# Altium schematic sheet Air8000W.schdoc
size 264 x 132 mm
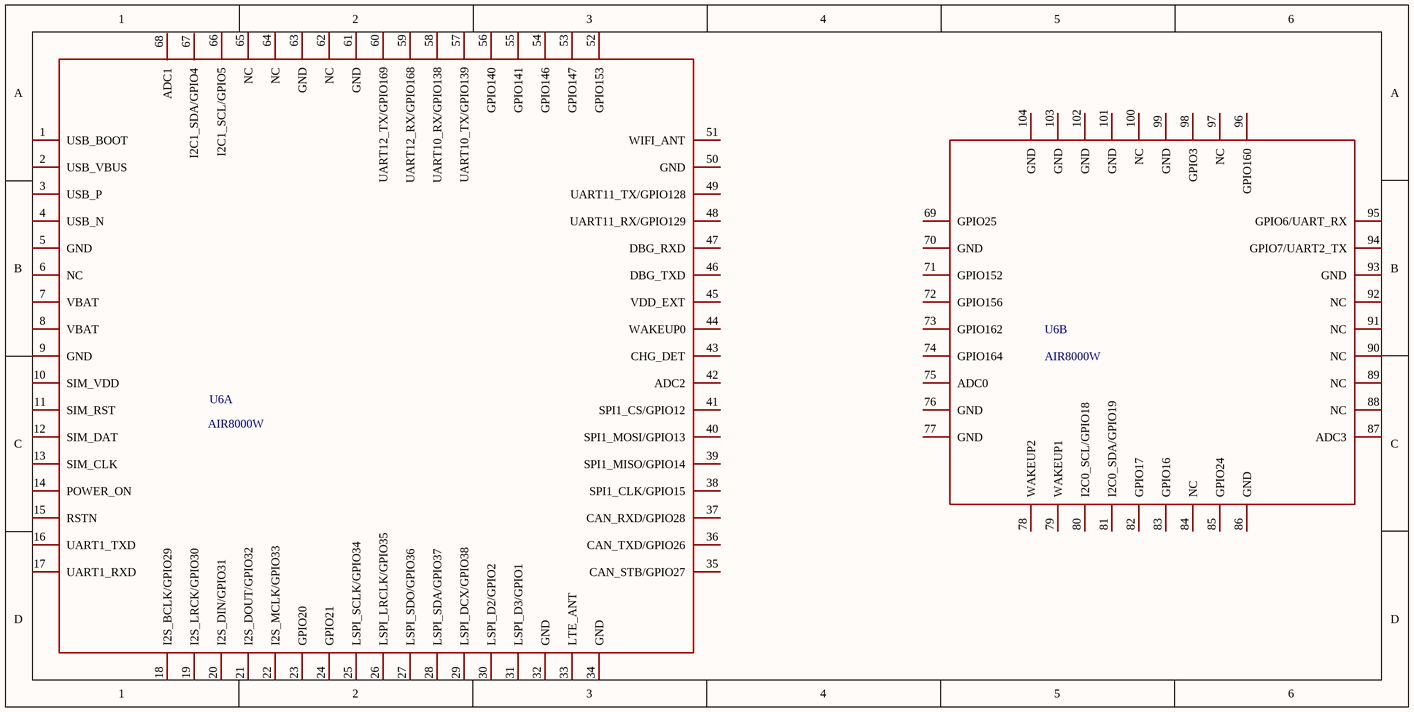
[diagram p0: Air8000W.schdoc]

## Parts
U6  AIR8000W  (parts A,B of 2)

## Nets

Not connected (* = marked no-connect by the designer): U6 1(USB_BOOT) 2(USB_VBUS) 3(USB_P) 4(USB_N) 5(GND) 6(NC) 7(VBAT) 8(VBAT) 9(GND) 10(SIM_VDD) 11(SIM_RST) 12(SIM_DAT) 13(SIM_CLK) 14(POWER_ON) 15(RSTN) 16(UART1_TXD) 17(UART1_RXD) 18(I2S_BCLK/GPIO29) 19(I2S_LRCK/GPIO30) 20(I2S_DIN/GPIO31) 21(I2S_DOUT/GPIO32) 22(I2S_MCLK/GPIO33) 23(GPIO20) 24(GPIO21) 25(LSPI_SCLK/GPIO34) 26(LSPI_LRCLK/GPIO35) 27(LSPI_SDO/GPIO36) 28(LSPI_SDA/GPIO37) 29(LSPI_DCX/GPIO38) 30(LSPI_D2/GPIO2) 31(LSPI_D3/GPIO1) 32(GND) 33(LTE_ANT) 34(GND) 35(CAN_STB/GPIO27) 36(CAN_TXD/GPIO26) 37(CAN_RXD/GPIO28) 38(SPI1_CLK/GPIO15) 39(SPI1_MISO/GPIO14) 40(SPI1_MOSI/GPIO13) 41(SPI1_CS/GPIO12) 42(ADC2) 43(CHG_DET) 44(WAKEUP0) 45(VDD_EXT) 46(DBG_TXD) 47(DBG_RXD) 48(UART11_RX/GPIO129) 49(UART11_TX/GPIO128) 50(GND) 51(WIFI_ANT) 52(GPIO153) 53(GPIO147) 54(GPIO146) 55(GPIO141) 56(GPIO140) 57(UART10_TX/GPIO139) 58(UART10_RX/GPIO138) 59(UART12_RX/GPIO168) 60(UART12_TX/GPIO169) 61(GND) 62(NC) 63(GND) 64(NC) 65(NC) 66(I2C1_SCL/GPIO5) 67(I2C1_SDA/GPIO4) 68(ADC1) 69(GPIO25) 70(GND) 71(GPIO152) 72(GPIO156) 73(GPIO162) 74(GPIO164) 75(ADC0) 76(GND) 77(GND) 78(WAKEUP2) 79(WAKEUP1) 80(I2C0_SCL/GPIO18) 81(I2C0_SDA/GPIO19) 82(GPIO17) 83(GPIO16) 84(NC) 85(GPIO24) 86(GND) 87(ADC3) 88(NC) 89(NC) 90(NC) 91(NC) 92(NC) 93(GND) 94(GPIO7/UART2_TX) 95(GPIO6/UART_RX) 96(GPIO160) 97(NC) 98(GPIO3) 99(GND) 100(NC) 101(GND) 102(GND) 103(GND) 104(GND)

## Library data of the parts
U6 = AIR8000W: Add into BOM: yes; Origin Footprint: AIR8000W-PADS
